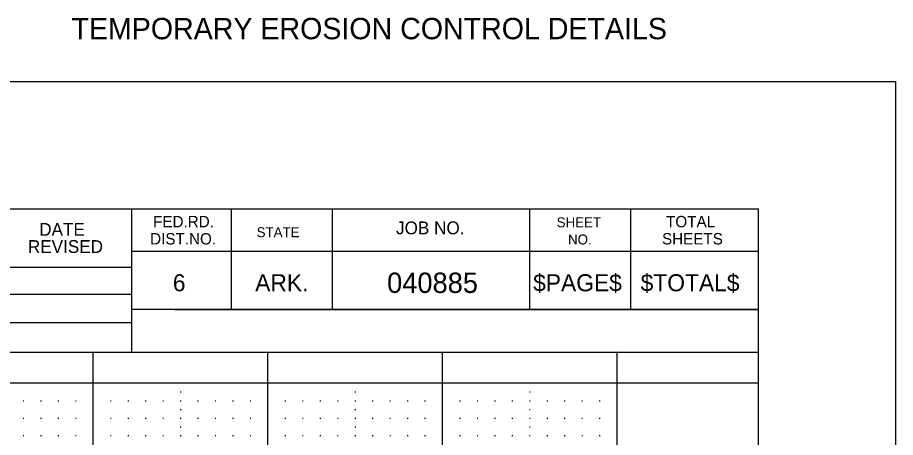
# Model space of a CAD drawing. Extents: x -1.6 to 32.4, y -1.9 to 21.6.
# Drawn here: x 27.37 to 32.4, y 19.23 to 21.64 of the extents above; entities that cross this region are included whole.
import ezdxf

# ---------------------------------------------------------------- set-up
doc = ezdxf.new("R2010")
doc.units = 0
for name, color, linetype in [('Level 1', 7, 'Continuous'), ('Level 4', 7, 'Continuous'), ('Level 5', 7, 'Continuous'), ('Level 61', 7, 'Continuous'), ('Level 63', 7, 'Continuous'), ('R_Border', 7, 'Continuous'), ('TYPICAL FONT', 7, 'Continuous')]:
    doc.layers.add(name, color=color, linetype=linetype)

msp = doc.modelspace()

# ---------------------------------------------------------------- linework, layer by layer
at = {"layer": 'Level 1'}
for p, q in [((-0.001, 20.545), (31.617, 20.545)), ((28.0268, 20.545), (28.0268, 19.7217)), ((28.5968, 20.545), (28.5968, 19.9667)), ((29.1751, 20.545), (29.1751, 19.9667)), ((30.3068, 20.545), (30.3068, 19.9667)), ((30.8851, 20.545), (30.8851, 19.9667)), ((31.617, -0.001), (31.617, 20.545)), ((31.6184, 20.3), (28.0268, 20.3)), ((31.6184, 20.3017), (31.6184, 20.3017)), ((26.3984, 20.21), (28.0268, 20.21)), ((26.3984, 20.055), (28.0268, 20.055)), ((31.6184, 19.9667), (28.0268, 19.9667)), ((28.2734, 19.9667), (31.6184, 19.9667)), ((26.3984, 19.8933), (28.0268, 19.8933)), ((31.6184, 19.7217), (26.3984, 19.7217))]:
    msp.add_line(p, q, dxfattribs=at)
at = {"layer": 'Level 4'}
for p, q in [((27.808, 0.545), (27.808, 19.7217)), ((28.808, 0.545), (28.808, 19.7217)), ((29.808, 0.545), (29.808, 19.7217)), ((30.808, 0.545), (30.808, 19.7217)), ((31.617, 19.545), (-0.001, 19.545))]:
    msp.add_line(p, q, dxfattribs=at)
at = {"layer": 'Level 5'}
for p, q in [((28.3055, 19.495), (28.3105, 19.495)), ((29.3055, 19.495), (29.3105, 19.495)), ((30.3055, 19.495), (30.3105, 19.495)), ((27.4055, 19.445), (27.4105, 19.445)), ((27.5055, 19.445), (27.5105, 19.445)), ((27.6055, 19.445), (27.6105, 19.445)), ((27.7055, 19.445), (27.7105, 19.445)), ((27.9055, 19.445), (27.9105, 19.445)), ((28.0055, 19.445), (28.0105, 19.445)), ((28.1055, 19.445), (28.1105, 19.445)), ((28.2055, 19.445), (28.2105, 19.445)), ((28.3055, 19.445), (28.3105, 19.445)), ((28.4055, 19.445), (28.4105, 19.445)), ((28.5055, 19.445), (28.5105, 19.445)), ((28.6055, 19.445), (28.6105, 19.445)), ((28.7055, 19.445), (28.7105, 19.445)), ((28.9055, 19.445), (28.9105, 19.445)), ((29.0055, 19.445), (29.0105, 19.445)), ((29.1055, 19.445), (29.1105, 19.445)), ((29.2055, 19.445), (29.2105, 19.445)), ((29.3055, 19.445), (29.3105, 19.445)), ((29.4055, 19.445), (29.4105, 19.445)), ((29.5055, 19.445), (29.5105, 19.445)), ((29.6055, 19.445), (29.6105, 19.445)), ((29.7055, 19.445), (29.7105, 19.445)), ((29.9055, 19.445), (29.9105, 19.445)), ((30.0055, 19.445), (30.0105, 19.445)), ((30.1055, 19.445), (30.1105, 19.445)), ((30.2055, 19.445), (30.2105, 19.445)), ((30.3055, 19.445), (30.3105, 19.445)), ((30.4055, 19.445), (30.4105, 19.445)), ((30.5055, 19.445), (30.5105, 19.445)), ((30.6055, 19.445), (30.6105, 19.445)), ((30.7055, 19.445), (30.7105, 19.445)), ((28.3055, 19.395), (28.3105, 19.395)), ((29.3055, 19.395), (29.3105, 19.395)), ((30.3055, 19.395), (30.3105, 19.395)), ((27.4055, 19.345), (27.4105, 19.345)), ((27.5055, 19.345), (27.5105, 19.345)), ((27.6055, 19.345), (27.6105, 19.345)), ((27.7055, 19.345), (27.7105, 19.345)), ((27.9055, 19.345), (27.9105, 19.345)), ((28.0055, 19.345), (28.0105, 19.345)), ((28.1055, 19.345), (28.1105, 19.345)), ((28.2055, 19.345), (28.2105, 19.345)), ((28.3055, 19.345), (28.3105, 19.345)), ((28.4055, 19.345), (28.4105, 19.345)), ((28.5055, 19.345), (28.5105, 19.345)), ((28.6055, 19.345), (28.6105, 19.345)), ((28.7055, 19.345), (28.7105, 19.345)), ((28.9055, 19.345), (28.9105, 19.345)), ((29.0055, 19.345), (29.0105, 19.345)), ((29.1055, 19.345), (29.1105, 19.345)), ((29.2055, 19.345), (29.2105, 19.345)), ((29.3055, 19.345), (29.3105, 19.345)), ((29.4055, 19.345), (29.4105, 19.345)), ((29.5055, 19.345), (29.5105, 19.345)), ((29.6055, 19.345), (29.6105, 19.345)), ((29.7055, 19.345), (29.7105, 19.345)), ((29.9055, 19.345), (29.9105, 19.345)), ((30.0055, 19.345), (30.0105, 19.345)), ((30.1055, 19.345), (30.1105, 19.345)), ((30.2055, 19.345), (30.2105, 19.345)), ((30.3055, 19.345), (30.3105, 19.345)), ((30.4055, 19.345), (30.4105, 19.345)), ((30.5055, 19.345), (30.5105, 19.345)), ((30.6055, 19.345), (30.6105, 19.345)), ((30.7055, 19.345), (30.7105, 19.345)), ((28.3055, 19.295), (28.3105, 19.295)), ((29.3055, 19.295), (29.3105, 19.295)), ((30.3055, 19.295), (30.3105, 19.295)), ((27.4055, 19.245), (27.4105, 19.245)), ((27.5055, 19.245), (27.5105, 19.245)), ((27.6055, 19.245), (27.6105, 19.245)), ((27.7055, 19.245), (27.7105, 19.245)), ((27.9055, 19.245), (27.9105, 19.245)), ((28.0055, 19.245), (28.0105, 19.245)), ((28.1055, 19.245), (28.1105, 19.245)), ((28.2055, 19.245), (28.2105, 19.245)), ((28.3055, 19.245), (28.3105, 19.245)), ((28.4055, 19.245), (28.4105, 19.245)), ((28.5055, 19.245), (28.5105, 19.245)), ((28.6055, 19.245), (28.6105, 19.245)), ((28.7055, 19.245), (28.7105, 19.245)), ((28.9055, 19.245), (28.9105, 19.245)), ((29.0055, 19.245), (29.0105, 19.245)), ((29.1055, 19.245), (29.1105, 19.245)), ((29.2055, 19.245), (29.2105, 19.245)), ((29.3055, 19.245), (29.3105, 19.245)), ((29.4055, 19.245), (29.4105, 19.245)), ((29.5055, 19.245), (29.5105, 19.245)), ((29.6055, 19.245), (29.6105, 19.245)), ((29.7055, 19.245), (29.7105, 19.245)), ((29.9055, 19.245), (29.9105, 19.245)), ((30.0055, 19.245), (30.0105, 19.245)), ((30.1055, 19.245), (30.1105, 19.245)), ((30.2055, 19.245), (30.2105, 19.245)), ((30.3055, 19.245), (30.3105, 19.245)), ((30.4055, 19.245), (30.4105, 19.245)), ((30.5055, 19.245), (30.5105, 19.245)), ((30.6055, 19.245), (30.6105, 19.245)), ((30.7055, 19.245), (30.7105, 19.245))]:
    msp.add_line(p, q, dxfattribs=at)
at = {"layer": 'Level 61'}
msp.add_lwpolyline([(0.808, 0.545), (30.808, 0.545), (30.8079, 19.7222), (26.3984, 19.7217), (26.3984, 19.7217), (26.3984, 19.7217), (26.3984, 19.7217), (26.3984, 19.7217), (26.3984, 20.545), (26.3984, 20.545), (26.3984, 20.545), (0.808, 20.545)], close=True, dxfattribs=at)
at = {"layer": 'Level 63'}
msp.add_lwpolyline([(-1.598, 21.273), (32.402, 21.273), (32.402, -0.727), (-1.598, -0.727)], close=True, dxfattribs=at)

# ---------------------------------------------------------------- texts
at = {"layer": 'Level 1'}
for s, height, p in [('FED.RD.', 0.06516, (28.1501, 20.4383)), ('SHEET', 0.057, (30.4618, 20.4383)), ('TOTAL', 0.06516, (31.0884, 20.4383)), ('DATE', 0.07327, (27.4982, 20.3897)), ('STATE', 0.057, (28.7434, 20.3817)), ('REVISED', 0.07327, (27.4332, 20.2914)), ('DIST.NO.', 0.06516, (28.1334, 20.34)), ('NO.', 0.057, (30.5268, 20.34)), ('SHEETS', 0.06516, (31.0651, 20.34)), ('6', 0.0977, (28.2634, 20.0717)), ('ARK.', 0.09769, (28.7351, 20.0717)), ('$PAGE$', 0.0977, (30.3268, 20.0717)), ('$TOTAL$', 0.0977, (30.9426, 20.0717))]:
    msp.add_text(s, height=height, dxfattribs=at).set_placement(p)
at = {"layer": 'R_Border'}
for s, height, p in [('JOB NO.', 0.07327, (29.5418, 20.3983)), ('JOB NO.', 0.07327, (29.5418, 20.3983)), ('040885', 0.11667, (29.4905, 20.0622))]:
    msp.add_text(s, height=height, dxfattribs=at).set_placement(p)
at = {"layer": 'TYPICAL FONT'}
msp.add_text('TEMPORARY EROSION CONTROL DETAILS', height=0.122398, dxfattribs=at).set_placement((27.6828, 21.5156))

doc.saveas('drawing.dxf')
